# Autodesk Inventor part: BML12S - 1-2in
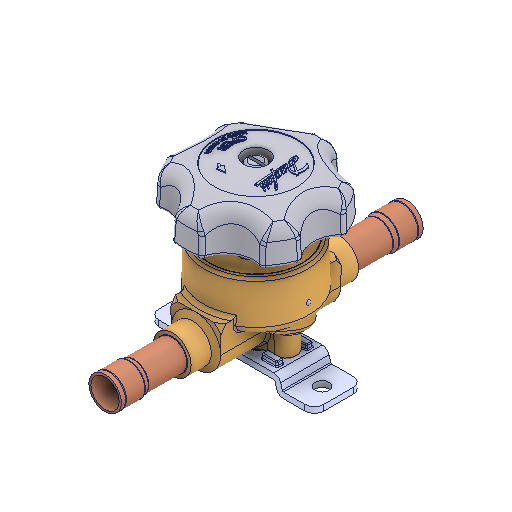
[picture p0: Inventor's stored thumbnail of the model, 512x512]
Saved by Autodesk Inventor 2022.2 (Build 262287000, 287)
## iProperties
Created: 2015-07
Part Number: BML12S - 1-2in
Material: Generico
Document SubType Name: Modeling
Designer: 18907419
Density: 1 g/cm^3
Appearance: Default
Author: 18907419
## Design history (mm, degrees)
feature "Solido1"
feature "Solido1:1"
node "Solido2"
node "Solido3"
